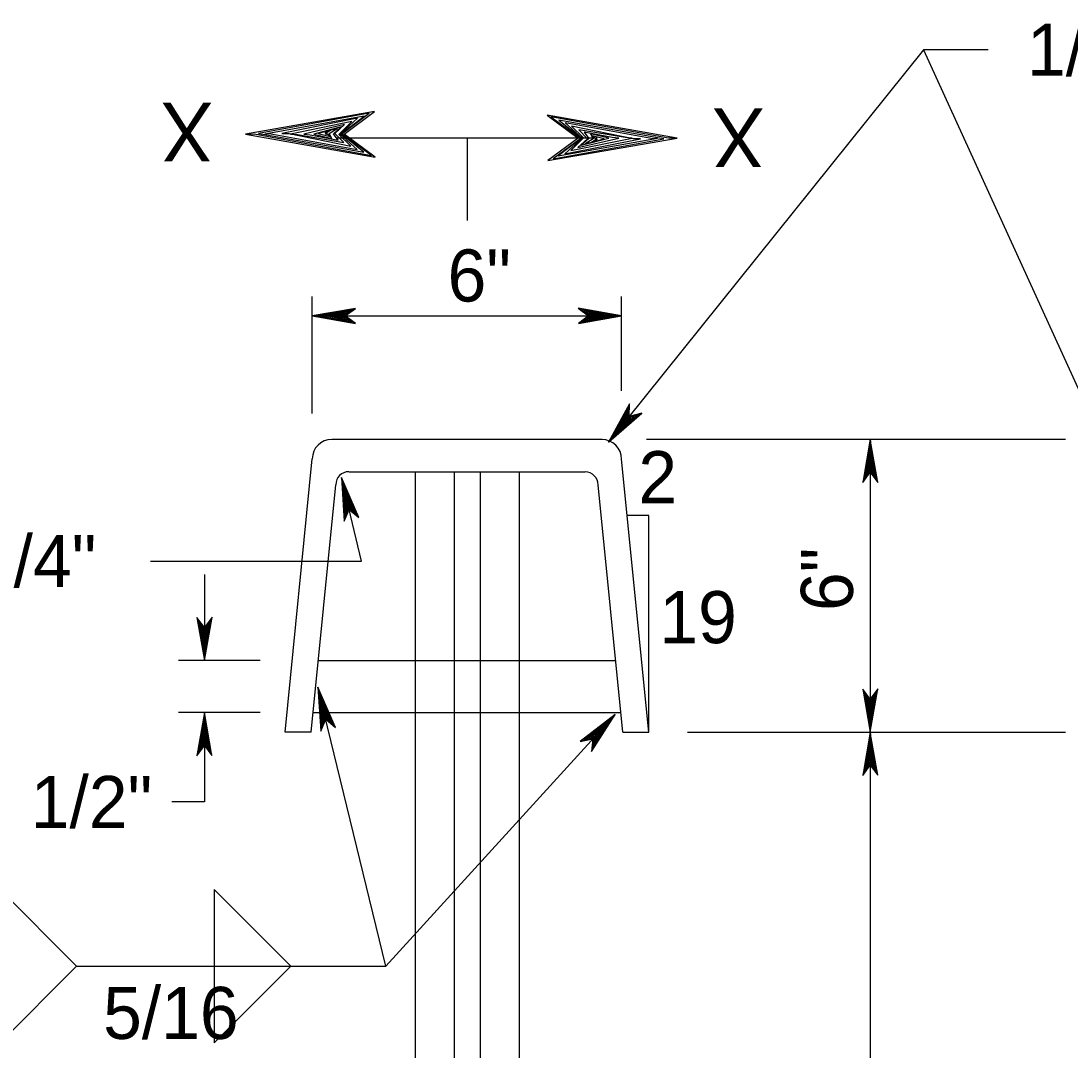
# Model space of a CAD drawing. Extents: x 499866 to 500993, y 499985 to 500645.
# Drawn here: x 500569.8 to 500650.4, y 500102.5 to 500181.6 of the extents above; entities that cross this region are included whole.
import ezdxf

# ---------------------------------------------------------------- set-up
doc = ezdxf.new("R2010")
doc.units = 0
for name, color, linetype in [('2', 7, 'Continuous'), ('24', 7, 'Continuous'), ('5', 7, 'Continuous')]:
    doc.layers.add(name, color=color, linetype=linetype)

msp = doc.modelspace()

# ---------------------------------------------------------------- linework, layer by layer
at = {"layer": '2'}
for p, q in [((500604.116, 500172.588), (500604.116, 500166.259)), ((500600.119, 500146.946), (500600.119, 500132.432)), ((500603.117, 500146.946), (500603.117, 500052.017)), ((500605.115, 500146.946), (500605.115, 500052.017)), ((500608.113, 500146.946), (500608.113, 500132.432)), ((500600.119, 500128.445), (500600.119, 500052.017)), ((500608.113, 500128.405), (500608.113, 500052.017))]:
    msp.add_line(p, q, dxfattribs=at)
at = {"layer": '24'}
for points in [[(500614.965, 500149.214), (500617.524, 500151.456), (500616.561, 500151.203), (500616.596, 500152.178), (500614.965, 500149.214), (500615.1, 500149.391), (500617.431, 500151.411), (500616.516, 500151.158), (500616.548, 500152.044), (500615.167, 500149.492), (500615.249, 500149.568), (500617.236, 500151.306), (500616.506, 500151.145), (500616.526, 500151.897), (500615.282, 500149.608), (500615.338, 500149.705), (500617.08, 500151.22), (500616.496, 500151.122), (500616.46, 500151.73), (500615.54, 500149.958), (500615.659, 500150.105), (500616.908, 500151.142), (500616.481, 500151.088), (500616.43, 500151.556), (500615.693, 500150.121), (500615.813, 500150.254), (500616.721, 500151.058), (500616.396, 500151.025), (500616.374, 500151.362), (500615.908, 500150.389), (500616.027, 500150.51), (500616.583, 500150.984), (500616.383, 500150.993), (500616.366, 500151.257), (500616.068, 500150.588), (500616.448, 500150.884), (500616.306, 500150.911), (500616.335, 500151.152), (500616.129, 500150.691), (500616.381, 500150.883), (500616.221, 500150.845), (500616.267, 500150.998), (500616.249, 500150.825), (500616.31, 500150.874)], [(500583.94, 500132.456), (500584.528, 500135.78), (500583.94, 500134.986), (500583.362, 500135.763), (500583.94, 500132.456), (500583.934, 500132.677), (500584.484, 500135.687), (500583.933, 500134.924), (500583.407, 500135.629), (500583.924, 500132.796), (500583.94, 500132.907), (500584.399, 500135.486), (500583.934, 500134.907), (500583.482, 500135.502), (500583.941, 500132.958), (500583.924, 500133.068), (500584.331, 500135.322), (500583.941, 500134.884), (500583.535, 500135.331), (500583.924, 500133.389), (500583.924, 500133.576), (500584.247, 500135.155), (500583.95, 500134.848), (500583.619, 500135.178), (500583.94, 500133.61), (500583.95, 500133.787), (500584.154, 500134.974), (500583.923, 500134.746), (500583.696, 500134.993), (500583.94, 500133.95), (500583.957, 500134.118), (500584.094, 500134.83), (500583.933, 500134.713), (500583.756, 500134.907), (500583.941, 500134.205), (500584.051, 500134.669), (500583.924, 500134.602), (500583.797, 500134.806), (500583.923, 500134.322), (500584, 500134.627), (500583.899, 500134.499), (500583.84, 500134.645), (500583.933, 500134.5), (500583.95, 500134.576)], [(500583.94, 500132.456), (500584.528, 500135.78), (500583.94, 500134.986), (500583.362, 500135.763), (500583.94, 500132.456), (500583.934, 500132.677), (500584.484, 500135.687), (500583.933, 500134.924), (500583.407, 500135.629), (500583.924, 500132.796), (500583.94, 500132.907), (500584.399, 500135.486), (500583.934, 500134.907), (500583.482, 500135.502), (500583.941, 500132.958), (500583.924, 500133.068), (500584.331, 500135.322), (500583.941, 500134.884), (500583.535, 500135.331), (500583.924, 500133.389), (500583.924, 500133.576), (500584.247, 500135.155), (500583.95, 500134.848), (500583.619, 500135.178), (500583.94, 500133.61), (500583.95, 500133.787), (500584.154, 500134.974), (500583.923, 500134.746), (500583.696, 500134.993), (500583.94, 500133.95), (500583.957, 500134.118), (500584.094, 500134.83), (500583.933, 500134.713), (500583.756, 500134.907), (500583.941, 500134.205), (500584.051, 500134.669), (500583.924, 500134.602), (500583.797, 500134.806), (500583.923, 500134.322), (500584, 500134.627), (500583.899, 500134.499), (500583.84, 500134.645), (500583.933, 500134.5), (500583.95, 500134.576)], [(500592.66, 500130.394), (500592.873, 500127.026), (500593.257, 500127.936), (500594.003, 500127.318), (500592.66, 500130.394), (500592.718, 500130.181), (500592.894, 500127.127), (500593.249, 500127.998), (500593.926, 500127.437), (500592.756, 500130.068), (500592.766, 500129.956), (500592.929, 500127.343), (500593.245, 500128.014), (500593.824, 500127.543), (500592.778, 500129.907), (500592.82, 500129.804), (500592.957, 500127.517), (500593.232, 500128.035), (500593.732, 500127.697), (500592.896, 500129.492), (500592.94, 500129.31), (500592.999, 500127.7), (500593.215, 500128.068), (500593.614, 500127.825), (500592.932, 500129.273), (500592.964, 500129.098), (500593.047, 500127.897), (500593.217, 500128.173), (500593.496, 500127.987), (500593.012, 500128.942), (500593.035, 500128.775), (500593.072, 500128.051), (500593.199, 500128.203), (500593.418, 500128.056), (500593.072, 500128.695), (500593.074, 500128.218), (500593.182, 500128.313), (500593.354, 500128.145), (500593.117, 500128.586), (500593.114, 500128.271), (500593.182, 500128.419), (500593.275, 500128.291), (500593.149, 500128.41), (500593.151, 500128.332)], [(500592.66, 500130.394), (500592.873, 500127.026), (500593.257, 500127.936), (500594.003, 500127.318), (500592.66, 500130.394), (500592.718, 500130.181), (500592.894, 500127.127), (500593.249, 500127.998), (500593.926, 500127.437), (500592.756, 500130.068), (500592.766, 500129.956), (500592.929, 500127.343), (500593.245, 500128.014), (500593.824, 500127.543), (500592.778, 500129.907), (500592.82, 500129.804), (500592.957, 500127.517), (500593.232, 500128.035), (500593.732, 500127.697), (500592.896, 500129.492), (500592.94, 500129.31), (500592.999, 500127.7), (500593.215, 500128.068), (500593.614, 500127.825), (500592.932, 500129.273), (500592.964, 500129.098), (500593.047, 500127.897), (500593.217, 500128.173), (500593.496, 500127.987), (500593.012, 500128.942), (500593.035, 500128.775), (500593.072, 500128.051), (500593.199, 500128.203), (500593.418, 500128.056), (500593.072, 500128.695), (500593.074, 500128.218), (500593.182, 500128.313), (500593.354, 500128.145), (500593.117, 500128.586), (500593.114, 500128.271), (500593.182, 500128.419), (500593.275, 500128.291), (500593.149, 500128.41), (500593.151, 500128.332)], [(500583.94, 500128.459), (500583.353, 500125.135), (500583.94, 500125.93), (500584.519, 500125.153), (500583.94, 500128.459), (500583.947, 500128.239), (500583.396, 500125.228), (500583.948, 500125.991), (500584.473, 500125.287), (500583.957, 500128.119), (500583.94, 500128.009), (500583.482, 500125.43), (500583.947, 500126.009), (500584.399, 500125.414), (500583.94, 500127.958), (500583.957, 500127.848), (500583.55, 500125.594), (500583.94, 500126.032), (500584.346, 500125.585), (500583.957, 500127.527), (500583.957, 500127.339), (500583.634, 500125.761), (500583.931, 500126.068), (500584.261, 500125.738), (500583.94, 500127.306), (500583.93, 500127.128), (500583.727, 500125.942), (500583.957, 500126.17), (500584.185, 500125.923), (500583.94, 500126.965), (500583.924, 500126.798), (500583.787, 500126.085), (500583.948, 500126.202), (500584.125, 500126.009), (500583.94, 500126.711), (500583.83, 500126.246), (500583.957, 500126.313), (500584.084, 500126.109), (500583.957, 500126.594), (500583.881, 500126.289), (500583.981, 500126.417), (500584.041, 500126.27), (500583.948, 500126.416), (500583.931, 500126.34)], [(500583.94, 500128.459), (500583.353, 500125.135), (500583.94, 500125.93), (500584.519, 500125.153), (500583.94, 500128.459), (500583.947, 500128.239), (500583.396, 500125.228), (500583.948, 500125.991), (500584.473, 500125.287), (500583.957, 500128.119), (500583.94, 500128.009), (500583.482, 500125.43), (500583.947, 500126.009), (500584.399, 500125.414), (500583.94, 500127.958), (500583.957, 500127.848), (500583.55, 500125.594), (500583.94, 500126.032), (500584.346, 500125.585), (500583.957, 500127.527), (500583.957, 500127.339), (500583.634, 500125.761), (500583.931, 500126.068), (500584.261, 500125.738), (500583.94, 500127.306), (500583.93, 500127.128), (500583.727, 500125.942), (500583.957, 500126.17), (500584.185, 500125.923), (500583.94, 500126.965), (500583.924, 500126.798), (500583.787, 500126.085), (500583.948, 500126.202), (500584.125, 500126.009), (500583.94, 500126.711), (500583.83, 500126.246), (500583.957, 500126.313), (500584.084, 500126.109), (500583.957, 500126.594), (500583.881, 500126.289), (500583.981, 500126.417), (500584.041, 500126.27), (500583.948, 500126.416), (500583.931, 500126.34)], [(500597.863, 500108.97), (500615.476, 500128.295)], [(500615.476, 500128.295), (500612.803, 500126.234), (500613.772, 500126.425), (500613.677, 500125.462), (500615.476, 500128.295), (500615.332, 500128.128), (500612.898, 500126.274), (500613.82, 500126.466), (500613.733, 500125.592), (500615.26, 500128.033), (500615.173, 500127.962), (500613.097, 500126.365), (500613.831, 500126.479), (500613.763, 500125.736), (500615.139, 500127.925), (500615.076, 500127.832), (500613.258, 500126.44), (500613.842, 500126.501), (500613.84, 500125.898), (500614.861, 500127.594), (500614.734, 500127.456), (500613.432, 500126.508), (500613.859, 500126.534), (500613.881, 500126.067), (500614.699, 500127.443), (500614.572, 500127.318), (500613.623, 500126.578), (500613.947, 500126.592), (500613.948, 500126.256), (500614.47, 500127.191), (500614.344, 500127.078), (500613.764, 500126.643), (500613.962, 500126.622), (500613.962, 500126.359), (500614.299, 500127.003), (500613.904, 500126.734), (500614.043, 500126.698), (500614, 500126.462), (500614.232, 500126.905), (500613.97, 500126.731), (500614.131, 500126.758), (500614.076, 500126.609), (500614.105, 500126.78), (500614.041, 500126.735)]]:
    msp.add_lwpolyline(points, dxfattribs=at)
at = {"layer": '5'}
for p, q in [((500639.165, 500179.37), (500652.643, 500149.817)), ((500604.116, 500172.588), (500594.124, 500172.588)), ((500614.108, 500172.588), (500604.116, 500172.588)), ((500592.224, 500151.438), (500592.224, 500160.405)), ((500615.978, 500153.169), (500615.978, 500160.405)), ((500592.224, 500158.922), (500615.978, 500158.922)), ((500593.723, 500149.444), (500614.48, 500149.444)), ((500617.891, 500149.444), (500650.074, 500149.444)), ((500635.085, 500149.444), (500635.085, 500126.95)), ((500590.127, 500126.96), (500592.224, 500147.941)), ((500618.076, 500126.95), (500615.978, 500147.93)), ((500595.052, 500146.946), (500613.179, 500146.946)), ((500592.125, 500126.96), (500594.025, 500145.957)), ((500616.078, 500126.95), (500614.178, 500145.946)), ((500618.076, 500143.6), (500616.472, 500143.6)), ((500618.076, 500126.95), (500618.076, 500143.6)), ((500583.94, 500139.062), (500583.94, 500132.456)), ((500583.94, 500139.062), (500583.94, 500132.456)), ((500588.218, 500132.456), (500581.942, 500132.456)), ((500588.218, 500132.456), (500581.942, 500132.456)), ((500592.669, 500132.456), (500615.495, 500132.456)), ((500600.119, 500132.432), (500600.119, 500128.445)), ((500608.113, 500132.432), (500608.113, 500128.405)), ((500597.863, 500108.97), (500592.66, 500130.394)), ((500588.218, 500128.459), (500581.942, 500128.459)), ((500588.218, 500128.459), (500581.942, 500128.459)), ((500588.218, 500128.459), (500581.942, 500128.459)), ((500583.94, 500128.459), (500583.94, 500123.373)), ((500592.27, 500128.459), (500615.888, 500128.459)), ((500592.125, 500126.96), (500590.127, 500126.96)), ((500616.078, 500126.95), (500618.076, 500126.95)), ((500621.053, 500126.95), (500650.074, 500126.95)), ((500635.085, 500126.95), (500635.085, 500052.017)), ((500568.232, 500114.861), (500574.122, 500108.97)), ((500584.676, 500114.861), (500590.567, 500108.97)), ((500584.676, 500114.861), (500584.676, 500103.08)), ((500574.122, 500108.97), (500568.232, 500103.08)), ((500574.122, 500108.97), (500590.567, 500108.97)), ((500590.567, 500108.97), (500584.676, 500103.08)), ((500590.567, 500108.97), (500597.863, 500108.97))]:
    msp.add_line(p, q, dxfattribs=at)
for points in [[(500644.125, 500179.37), (500639.165, 500179.37), (500614.965, 500149.214)], [(500587.083, 500172.889), (500597.055, 500171.127), (500594.673, 500172.889), (500597.004, 500174.625), (500587.083, 500172.889), (500587.746, 500172.908), (500596.776, 500171.258), (500594.486, 500172.911), (500596.6, 500174.488), (500588.103, 500172.939), (500588.435, 500172.889), (500596.171, 500171.515), (500594.435, 500172.91), (500596.22, 500174.264), (500588.587, 500172.889), (500588.918, 500172.939), (500595.68, 500171.719), (500594.365, 500172.889), (500595.707, 500174.106), (500589.881, 500172.94), (500590.444, 500172.94), (500595.178, 500171.97), (500594.258, 500172.862), (500595.249, 500173.853), (500590.544, 500172.889), (500591.077, 500172.859), (500594.637, 500172.249), (500593.952, 500172.941), (500594.694, 500173.623), (500591.566, 500172.889), (500592.069, 500172.839), (500594.206, 500172.43), (500593.854, 500172.911), (500594.437, 500173.444), (500592.329, 500172.888), (500593.722, 500172.558), (500593.522, 500172.94), (500594.133, 500173.322), (500592.68, 500172.941), (500593.594, 500172.711), (500593.211, 500173.012), (500593.651, 500173.192), (500593.213, 500172.911), (500593.443, 500172.862)], [(500620.24, 500172.588), (500610.269, 500174.351), (500612.651, 500172.588), (500610.32, 500170.853), (500620.24, 500172.588), (500619.578, 500172.57), (500610.548, 500174.22), (500612.837, 500172.567), (500610.723, 500170.99), (500619.22, 500172.539), (500618.888, 500172.588), (500611.153, 500173.963), (500612.889, 500172.568), (500611.104, 500171.214), (500618.737, 500172.589), (500618.406, 500172.539), (500611.643, 500173.759), (500612.959, 500172.589), (500611.616, 500171.372), (500617.442, 500172.538), (500616.88, 500172.538), (500612.145, 500173.508), (500613.066, 500172.616), (500612.074, 500171.625), (500616.78, 500172.588), (500616.247, 500172.619), (500612.687, 500173.228), (500613.371, 500172.537), (500612.63, 500171.855), (500615.758, 500172.588), (500615.255, 500172.638), (500613.118, 500173.047), (500613.469, 500172.567), (500612.887, 500172.034), (500614.995, 500172.59), (500613.601, 500172.92), (500613.802, 500172.538), (500613.19, 500172.156), (500614.644, 500172.537), (500613.729, 500172.767), (500614.112, 500172.465), (500613.673, 500172.285), (500614.11, 500172.567), (500613.881, 500172.616)], [(500592.224, 500158.922), (500595.549, 500158.334), (500594.755, 500158.922), (500595.531, 500159.5), (500592.224, 500158.922), (500592.446, 500158.928), (500595.455, 500158.378), (500594.692, 500158.929), (500595.397, 500159.454), (500592.565, 500158.938), (500592.675, 500158.922), (500595.254, 500158.464), (500594.675, 500158.928), (500595.27, 500159.38), (500592.726, 500158.922), (500592.836, 500158.938), (500595.09, 500158.531), (500594.652, 500158.922), (500595.099, 500159.327), (500593.157, 500158.939), (500593.344, 500158.938), (500594.923, 500158.615), (500594.616, 500158.912), (500594.947, 500159.243), (500593.378, 500158.922), (500593.556, 500158.911), (500594.743, 500158.708), (500594.514, 500158.939), (500594.761, 500159.166), (500593.719, 500158.922), (500593.886, 500158.905), (500594.599, 500158.769), (500594.482, 500158.929), (500594.676, 500159.106), (500593.973, 500158.921), (500594.438, 500158.811), (500594.371, 500158.938), (500594.574, 500159.066), (500594.09, 500158.939), (500594.395, 500158.862), (500594.267, 500158.963), (500594.414, 500159.023), (500594.268, 500158.929), (500594.344, 500158.912)], [(500615.978, 500158.922), (500612.655, 500159.509), (500613.448, 500158.922), (500612.672, 500158.344), (500615.978, 500158.922), (500615.758, 500158.915), (500612.748, 500159.466), (500613.511, 500158.915), (500612.806, 500158.389), (500615.639, 500158.905), (500615.528, 500158.922), (500612.949, 500159.38), (500613.528, 500158.915), (500612.933, 500158.464), (500615.477, 500158.922), (500615.367, 500158.905), (500613.113, 500159.312), (500613.551, 500158.922), (500613.104, 500158.517), (500615.046, 500158.905), (500614.858, 500158.905), (500613.28, 500159.228), (500613.587, 500158.931), (500613.257, 500158.6), (500614.825, 500158.922), (500614.647, 500158.932), (500613.461, 500159.135), (500613.689, 500158.905), (500613.442, 500158.677), (500614.484, 500158.922), (500614.317, 500158.939), (500613.604, 500159.075), (500613.722, 500158.915), (500613.527, 500158.737), (500614.23, 500158.922), (500613.765, 500159.032), (500613.832, 500158.905), (500613.629, 500158.778), (500614.113, 500158.905), (500613.808, 500158.981), (500613.936, 500158.881), (500613.789, 500158.821), (500613.935, 500158.915), (500613.859, 500158.931)], [(500635.085, 500149.444), (500634.498, 500146.119), (500635.085, 500146.913), (500635.663, 500146.137), (500635.085, 500149.444), (500635.092, 500149.222), (500634.541, 500146.213), (500635.092, 500146.976), (500635.618, 500146.271), (500635.102, 500149.103), (500635.085, 500148.993), (500634.627, 500146.414), (500635.092, 500146.993), (500635.543, 500146.398), (500635.085, 500148.942), (500635.102, 500148.832), (500634.695, 500146.578), (500635.085, 500147.016), (500635.49, 500146.569), (500635.102, 500148.511), (500635.102, 500148.323), (500634.779, 500146.745), (500635.076, 500147.052), (500635.406, 500146.721), (500635.085, 500148.29), (500635.075, 500148.112), (500634.872, 500146.925), (500635.102, 500147.154), (500635.33, 500146.906), (500635.085, 500147.949), (500635.068, 500147.781), (500634.932, 500147.069), (500635.092, 500147.186), (500635.27, 500146.992), (500635.085, 500147.695), (500634.974, 500147.23), (500635.102, 500147.297), (500635.229, 500147.094), (500635.102, 500147.578), (500635.026, 500147.273), (500635.126, 500147.401), (500635.186, 500147.255), (500635.092, 500147.4), (500635.076, 500147.324)], [(500579.788, 500140.091), (500596.006, 500140.091), (500594.469, 500146.521)], [(500594.469, 500146.521), (500594.67, 500143.151), (500595.057, 500144.06), (500595.8, 500143.439), (500594.469, 500146.521), (500594.526, 500146.307), (500594.691, 500143.252), (500595.049, 500144.122), (500595.724, 500143.559), (500594.564, 500146.194), (500594.573, 500146.082), (500594.727, 500143.468), (500595.045, 500144.139), (500595.622, 500143.665), (500594.585, 500146.033), (500594.627, 500145.93), (500594.755, 500143.643), (500595.033, 500144.159), (500595.531, 500143.819), (500594.702, 500145.617), (500594.745, 500145.435), (500594.798, 500143.825), (500595.015, 500144.192), (500595.414, 500143.948), (500594.737, 500145.399), (500594.768, 500145.223), (500594.846, 500144.022), (500595.017, 500144.297), (500595.296, 500144.11), (500594.816, 500145.067), (500594.839, 500144.901), (500594.872, 500144.176), (500595, 500144.327), (500595.218, 500144.179), (500594.875, 500144.82), (500594.876, 500144.342), (500594.984, 500144.437), (500595.155, 500144.268), (500594.919, 500144.71), (500594.915, 500144.396), (500594.983, 500144.543), (500595.076, 500144.415), (500594.95, 500144.535), (500594.952, 500144.456)], [(500635.085, 500126.95), (500635.673, 500130.274), (500635.085, 500129.48), (500634.507, 500130.257), (500635.085, 500126.95), (500635.079, 500127.171), (500635.629, 500130.18), (500635.078, 500129.417), (500634.552, 500130.122), (500635.069, 500127.29), (500635.085, 500127.401), (500635.543, 500129.979), (500635.078, 500129.401), (500634.627, 500129.995), (500635.086, 500127.451), (500635.069, 500127.561), (500635.475, 500129.816), (500635.086, 500129.377), (500634.68, 500129.824), (500635.068, 500127.883), (500635.069, 500128.07), (500635.392, 500129.648), (500635.094, 500129.341), (500634.764, 500129.672), (500635.085, 500128.103), (500635.095, 500128.281), (500635.299, 500129.468), (500635.068, 500129.24), (500634.841, 500129.487), (500635.085, 500128.444), (500635.102, 500128.612), (500635.238, 500129.324), (500635.078, 500129.207), (500634.901, 500129.401), (500635.086, 500128.698), (500635.196, 500129.163), (500635.069, 500129.096), (500634.942, 500129.3), (500635.068, 500128.815), (500635.145, 500129.12), (500635.044, 500128.992), (500634.984, 500129.139), (500635.078, 500128.993), (500635.094, 500129.07)], [(500583.94, 500128.459), (500583.94, 500121.584), (500581.442, 500121.584)], [(500635.085, 500126.95), (500634.498, 500123.626), (500635.085, 500124.42), (500635.663, 500123.643), (500635.085, 500126.95), (500635.092, 500126.729), (500634.541, 500123.719), (500635.092, 500124.482), (500635.618, 500123.777), (500635.102, 500126.61), (500635.085, 500126.499), (500634.627, 500123.921), (500635.092, 500124.499), (500635.543, 500123.905), (500635.085, 500126.448), (500635.102, 500126.338), (500634.695, 500124.084), (500635.085, 500124.523), (500635.49, 500124.075), (500635.102, 500126.017), (500635.102, 500125.83), (500634.779, 500124.251), (500635.076, 500124.558), (500635.406, 500124.228), (500635.085, 500125.796), (500635.075, 500125.619), (500634.872, 500124.432), (500635.102, 500124.66), (500635.33, 500124.413), (500635.085, 500125.456), (500635.068, 500125.288), (500634.932, 500124.576), (500635.092, 500124.693), (500635.27, 500124.499), (500635.085, 500125.201), (500634.974, 500124.737), (500635.102, 500124.804), (500635.229, 500124.6), (500635.102, 500125.084), (500635.026, 500124.779), (500635.126, 500124.907), (500635.186, 500124.761), (500635.092, 500124.906), (500635.076, 500124.83)]]:
    msp.add_lwpolyline(points, dxfattribs=at)
for centre, radius, start, end in [((500593.723, 500147.941), 1.499, 90, 180), ((500614.48, 500147.93), 1.499, 0, 90), ((500595.024, 500145.957), 0.999, 90, 180), ((500613.179, 500145.946), 0.999, 0, 90)]:
    msp.add_arc(centre, radius, start, end, dxfattribs=at)

# ---------------------------------------------------------------- texts
for s, p in [('1/2" PLATE', (500647.125, 500177.37)), ('6"', (500602.614, 500160.032)), ('2', (500617.267, 500144.538)), ('R=3/4"', (500559.319, 500138.091)), ('19', (500618.882, 500133.783)), ('1/2"', (500570.6, 500119.584)), ('5/16', (500576.155, 500103.381))]:
    msp.add_text(s, height=4, dxfattribs=at).set_placement(p)
for s, height, rotation, p in [('X', 4.5, 180, (500584.605, 500175.312)), ('X', 4.5, 180, (500626.955, 500174.86)), ('6"', 4, 90, (500633.748, 500136.253))]:
    msp.add_text(s, height=height, rotation=rotation, dxfattribs=at).set_placement(p)

doc.saveas('drawing.dxf')
